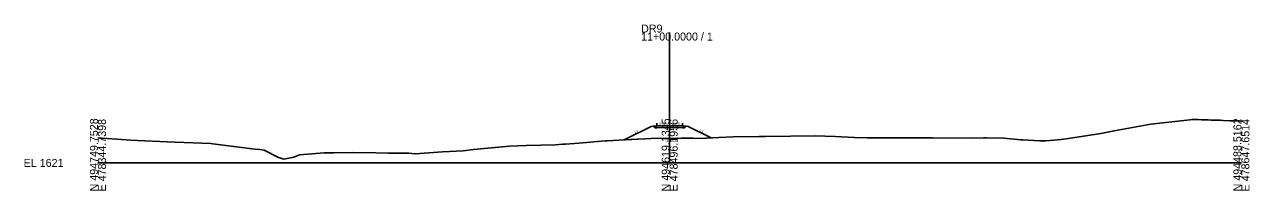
# Model space of a CAD drawing. Extents: x -26 to 403, y -10 to 1525.
# Drawn here: x -25.7 to 402.8, y 990.3 to 1048.5 of the extents above; entities that cross this region are included whole.
import ezdxf

# ---------------------------------------------------------------- set-up
doc = ezdxf.new("R2010")
doc.units = 0
for name, color, linetype in [('Exist Cross Section Cell', 7, 'Continuous'), ('Exist XS Center Line Elevation Label', 7, 'Continuous'), ('Exist XS Ground Line', 7, 'Continuous'), ('Prop XS Dump Level', 7, 'Continuous'), ('Prop XS Earthwork Shape', 7, 'Continuous'), ('Prop XS EOT Tick Mark', 7, 'Continuous'), ('Prop XS Finish Grade', 7, 'Continuous'), ('Prop XS Finish Grade Earthwork', 7, 'Continuous'), ('Prop XS Finish Grade Pavement', 7, 'Continuous'), ('Prop XS Pvmt Edge Slope', 7, 'Continuous'), ('Prop XS SE Text', 7, 'Continuous'), ('Prop XS Shoulder Borrow Shape', 7, 'Continuous'), ('Prop XS Side Slope Text', 7, 'Continuous'), ('Prop XS Subgrade Earthwork', 7, 'Continuous'), ('Scratch_Level_5', 7, 'Continuous')]:
    doc.layers.add(name, color=color, linetype=linetype)

msp = doc.modelspace()

# ---------------------------------------------------------------- linework, layer by layer
at = {"layer": 'Exist Cross Section Cell'}
for p, q in [((200, 1000), (200, 1045.69)), ((0, 1000), (200, 1000)), ((200, 1000), (400, 1000))]:
    msp.add_line(p, q, dxfattribs=at)
at = {"layer": 'Exist XS Ground Line'}
msp.add_lwpolyline([(0, 1008.8), (11.53, 1008.01), (13.82, 1007.88), (24.19, 1007.39), (27.02, 1007.26), (39.51, 1006.75), (40.23, 1006.71), (54.91, 1004.87), (56.66, 1004.67), (58.2, 1004.44), (62.95, 1001.96), (64.98, 1001.26), (68.52, 1001.98), (70.54, 1002.87), (79.1, 1003.52), (82.54, 1003.52), (89.02, 1003.62), (97.19, 1003.48), (101.57, 1003.44), (108.79, 1003.37), (111.01, 1003.18), (120.59, 1003.83), (127.82, 1004.28), (131.43, 1004.75), (143.95, 1005.86), (149.83, 1006.11), (160.12, 1006.28), (162.5, 1006.53), (163.58, 1006.53), (168.17, 1006.89), (177.42, 1007.7), (178.26, 1007.78), (182.27, 1007.95), (195.91, 1008.69), (199.11, 1008.61), (200, 1008.61), (204.08, 1008.62), (208.21, 1008.68), (210.84, 1008.59), (217.22, 1008.88), (222.18, 1009.1), (231.3, 1009.23), (233.52, 1009.27), (250.93, 1009.49), (257.86, 1009.31), (264.61, 1008.96), (269.12, 1008.81), (274.88, 1008.84), (279.4, 1008.78), (290.8, 1008.75), (291.96, 1008.76), (305.69, 1008.63), (309.79, 1008.73), (310.81, 1008.76), (316.88, 1008.71), (322.86, 1008.08), (323.51, 1008.04), (329.52, 1007.77), (331.56, 1007.74), (336.98, 1008.2), (339.58, 1008.58), (350.89, 1010.32), (355.49, 1011.25), (368.37, 1013.55), (381.91, 1015.13), (382.71, 1015.23), (383.7, 1015.19), (384.89, 1015.17), (386.07, 1015.13), (386.5, 1015.12), (388.12, 1015.07), (388.43, 1015.06), (389.38, 1015.02), (389.84, 1015.01), (391.08, 1014.97), (392.67, 1014.92), (393.63, 1014.89), (395.99, 1014.8), (396.67, 1014.78), (397.46, 1014.76), (399.3, 1014.69), (400, 1014.67)], dxfattribs=at)
at = {"layer": 'Prop XS Dump Level'}
for p, q in [((195.5, 1012.94), (200, 1013.03)), ((200, 1013.03), (204.5, 1012.94))]:
    msp.add_line(p, q, dxfattribs=at)
at = {"layer": 'Prop XS Earthwork Shape'}
msp.add_lwpolyline([(193.5, 1012.78), (184.05, 1008.05), (195.91, 1008.69), (199.11, 1008.61), (200, 1008.61), (204.08, 1008.62), (208.21, 1008.68), (210.84, 1008.59), (214.54, 1008.76), (206.5, 1012.78), (205.76, 1012.84), (205.18, 1012.26), (204.5, 1012.27), (200, 1012.36), (195.5, 1012.27), (194.82, 1012.26), (194.24, 1012.84)], close=True, dxfattribs=at)
at = {"layer": 'Prop XS EOT Tick Mark'}
for p, q in [((195.5, 1012.94), (195.5, 1013.94)), ((204.5, 1012.94), (204.5, 1013.94))]:
    msp.add_line(p, q, dxfattribs=at)
at = {"layer": 'Prop XS Finish Grade'}
for p, q in [((195.5, 1012.94), (194.24, 1012.84)), ((204.5, 1012.94), (205.76, 1012.84))]:
    msp.add_line(p, q, dxfattribs=at)
at = {"layer": 'Prop XS Finish Grade Earthwork'}
for p, q in [((193.5, 1012.78), (184.05, 1008.05)), ((194.24, 1012.84), (193.5, 1012.78)), ((205.76, 1012.84), (206.5, 1012.78)), ((206.5, 1012.78), (214.54, 1008.76))]:
    msp.add_line(p, q, dxfattribs=at)
at = {"layer": 'Prop XS Finish Grade Pavement'}
for p, q in [((195.5, 1012.94), (200, 1013.03)), ((200, 1013.03), (204.5, 1012.94))]:
    msp.add_line(p, q, dxfattribs=at)
at = {"layer": 'Prop XS Pvmt Edge Slope'}
for p, q in [((195.5, 1012.94), (194.82, 1012.26)), ((204.5, 1012.94), (205.18, 1012.26))]:
    msp.add_line(p, q, dxfattribs=at)
at = {"layer": 'Prop XS Shoulder Borrow Shape'}
for points in [[(195.5, 1012.94), (194.24, 1012.84), (194.82, 1012.26)], [(204.5, 1012.94), (205.76, 1012.84), (205.18, 1012.26)]]:
    msp.add_lwpolyline(points, close=True, dxfattribs=at)
at = {"layer": 'Prop XS Subgrade Earthwork'}
for p, q in [((194.82, 1012.26), (194.24, 1012.84)), ((195.5, 1012.27), (194.82, 1012.26)), ((200, 1012.36), (195.5, 1012.27)), ((204.5, 1012.27), (200, 1012.36)), ((204.5, 1012.27), (205.18, 1012.26)), ((205.18, 1012.26), (205.76, 1012.84))]:
    msp.add_line(p, q, dxfattribs=at)
at = {"layer": 'Scratch_Level_5'}
msp.add_lwpolyline([(0, 1008.8), (11.53, 1008.01), (13.82, 1007.88), (24.19, 1007.39), (27.02, 1007.26), (39.51, 1006.75), (40.23, 1006.71), (54.91, 1004.87), (56.66, 1004.67), (58.2, 1004.44), (62.95, 1001.96), (64.98, 1001.26), (68.52, 1001.98), (70.54, 1002.87), (79.1, 1003.52), (82.54, 1003.52), (89.02, 1003.62), (97.19, 1003.48), (101.57, 1003.44), (108.79, 1003.37), (111.01, 1003.18), (120.59, 1003.83), (127.82, 1004.28), (131.43, 1004.75), (143.95, 1005.86), (149.83, 1006.11), (160.12, 1006.28), (162.5, 1006.53), (163.58, 1006.53), (168.17, 1006.89), (177.42, 1007.7), (178.26, 1007.78), (182.27, 1007.95), (195.91, 1008.69), (199.11, 1008.61), (200, 1008.61), (204.08, 1008.62), (208.21, 1008.68), (210.84, 1008.59), (217.22, 1008.88), (222.18, 1009.1), (231.3, 1009.23), (233.52, 1009.27), (250.93, 1009.49), (257.86, 1009.31), (264.61, 1008.96), (269.12, 1008.81), (274.88, 1008.84), (279.4, 1008.78), (290.8, 1008.75), (291.96, 1008.76), (305.69, 1008.63), (309.79, 1008.73), (310.81, 1008.76), (316.88, 1008.71), (322.86, 1008.08), (323.51, 1008.04), (329.52, 1007.77), (331.56, 1007.74), (336.98, 1008.2), (339.58, 1008.58), (350.89, 1010.32), (355.49, 1011.25), (368.37, 1013.55), (381.91, 1015.13), (382.71, 1015.23), (383.7, 1015.19), (384.89, 1015.17), (386.07, 1015.13), (386.5, 1015.12), (388.12, 1015.07), (388.43, 1015.06), (389.38, 1015.02), (389.84, 1015.01), (391.08, 1014.97), (392.67, 1014.92), (393.63, 1014.89), (395.99, 1014.8), (396.67, 1014.78), (397.46, 1014.76), (399.3, 1014.69), (400, 1014.67)], dxfattribs=at)

# ---------------------------------------------------------------- texts
at = {"layer": 'Exist Cross Section Cell'}
for s, p in [('11+00.0000 / 1', (190, 1042.89)), ('DR9', (190, 1045.69)), ('EL 1621', (-26, 998.6))]:
    msp.add_text(s, height=2.8, dxfattribs=at).set_placement(p)
for s, p in [('N 494749.7528', (0, 990)), ('E 478344.7398', (2.8, 990)), ('N 494619.1345', (200, 990)), ('E 478496.1956', (202.8, 990)), ('N 494488.5162', (400, 990)), ('E 478647.6514', (402.8, 990))]:
    msp.add_text(s, height=2.8, rotation=90, dxfattribs=at).set_placement(p)
at = {"layer": 'Exist XS Center Line Elevation Label'}
msp.add_text('1629.61', height=0.75, dxfattribs=at).set_placement((198.41, 1007.36))
at = {"layer": 'Prop XS Dump Level'}
for p in [(193.5, 1012.74), (206.5, 1012.74)]:
    msp.add_text('Case1', height=0.04, dxfattribs=at).set_placement(p)
at = {"layer": 'Prop XS SE Text'}
for rotation, p in [(1.1458, (196.44, 1013.35)), (358.8542, (200.94, 1013.41))]:
    msp.add_text('0.020', height=0.75, rotation=rotation, dxfattribs=at).set_placement(p)
at = {"layer": 'Prop XS Side Slope Text'}
for rotation, p in [(23.8531, (187.82, 1010.28)), (333.4349, (210.4, 1011.25))]:
    msp.add_text('2:1', height=0.75, rotation=rotation, dxfattribs=at).set_placement(p)

doc.saveas('drawing.dxf')
